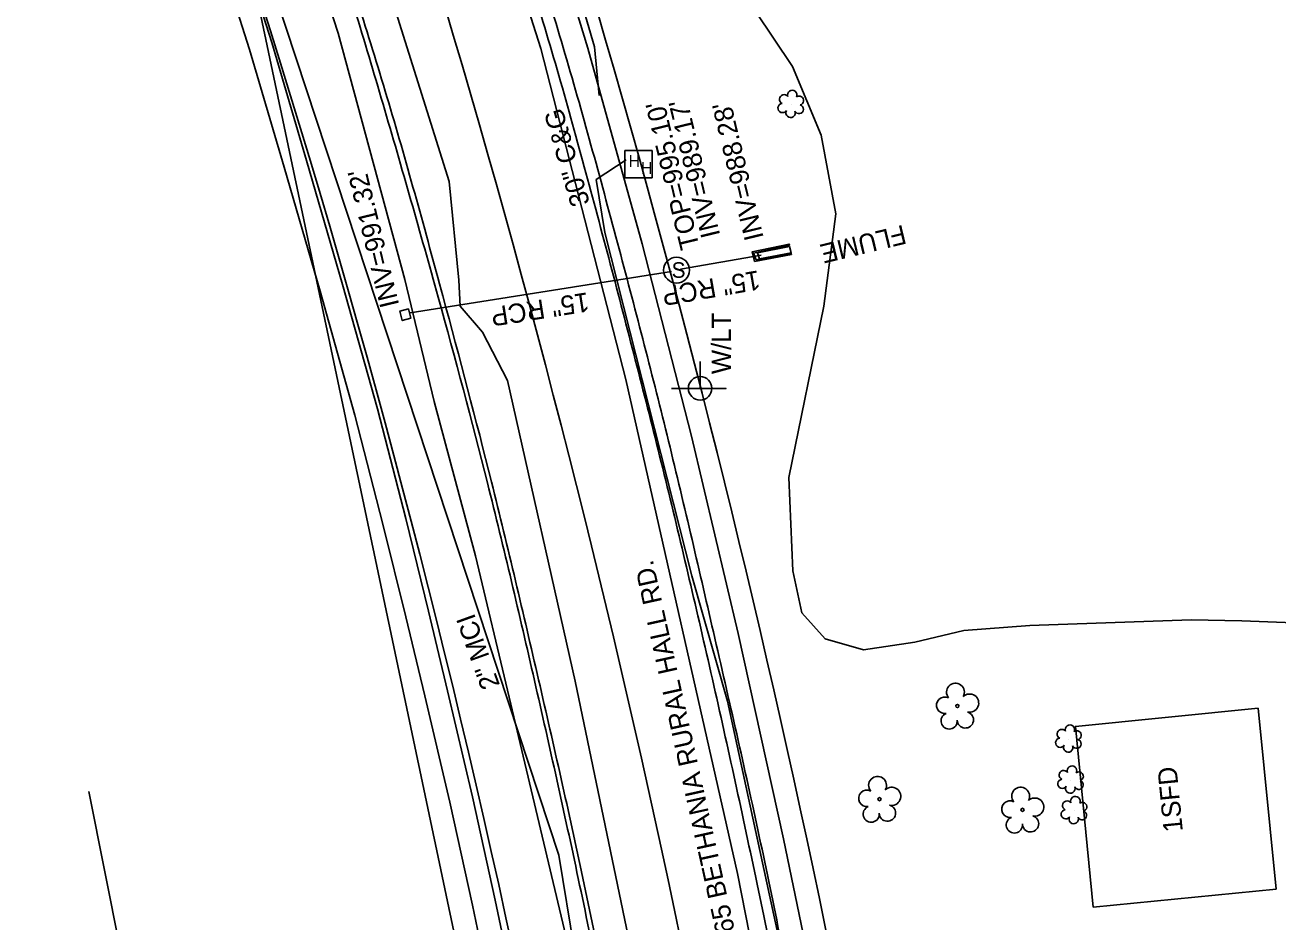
# Model space of a CAD drawing. Extents: x 1614611 to 1617571, y 898867 to 905462.
# Drawn here: x 1616509.7 to 1616770.7, y 902671.5 to 902858.4 of the extents above; entities that cross this region are included whole.
import ezdxf

# ---------------------------------------------------------------- set-up
doc = ezdxf.new("R2010")
doc.units = 0
for name, color, linetype in [('Exist Boundary Watershed Impervious C 09', 7, 'Continuous'), ('Exist Boundary Watershed Residential C 05', 7, 'Continuous'), ('Exist Building', 7, 'Continuous'), ('Exist Building Text', 7, 'Continuous'), ('Exist Roads Curbs Text', 7, 'Continuous'), ('Exist Roads EOP Text', 7, 'Continuous'), ('Exist Structure Minor Head and End Wall Text', 7, 'Continuous'), ('Exist Structure Minor Pipes RCP 15 Inch Invert', 7, 'Continuous'), ('Exist Structure Minor Storm Sewer Manhole Top Elevation', 7, 'Continuous'), ('Exist Utilities Gas UG Line SUE LOS B', 7, 'Continuous'), ('Exist Utilities Power Joint Use Telephone CELL', 7, 'Continuous'), ('Exist Utilities Power Joint Use Telephone Text', 7, 'Continuous'), ('Exist Utilities Telephone Hand Hole CELL', 7, 'Continuous'), ('Exist Utilities Telephone UG Cable SUE LOS B', 7, 'Continuous'), ('Exist Utilities Telephone UG FO SUE LOS B', 7, 'Continuous'), ('Exist Utilities Telephone UG FO SUE LOS C', 7, 'Continuous'), ('Exist Utilities Telephone UG FO SUE LOS C Text', 7, 'Continuous'), ('Exist Utilities Water UG Line SUE LOS B', 7, 'Continuous'), ('Exist Vegetation Shrub CELL', 7, 'Continuous'), ('Exist Vegetation Tree CELL', 7, 'Continuous'), ('Exist Vegetation Woods Line', 7, 'Continuous'), ('Prop Drainage Structure Pipe RCP 15in Class IV', 7, 'Continuous'), ('Prop Drainage Structure Pipe RCP 24in Class IV', 7, 'Continuous'), ('Prop Earthen Structure Head Ditch Label', 7, 'Continuous'), ('Prop Erosion Embankment Toe Protection CELL', 7, 'Continuous'), ('Prop Erosion Embankment Toe Protection with Rip Rap 2 Detail CELL', 7, 'Continuous'), ('Prop Plan Preparation Table Ditch Data CELL', 7, 'Continuous'), ('Raster_Level_2', 7, 'Continuous'), ('Scratch_Level_1', 7, 'Continuous'), ('Scratch_Level_9', 7, 'Continuous')]:
    doc.layers.add(name, color=color, linetype=linetype)

# ---------------------------------------------------------------- blocks, each defined once
blk = doc.blocks.new('EXIST STRUCTURE MINOR STORM SEWER MANHOLE')
at = {"layer": 'Prop Drainage Structure Pipe RCP 15in Class IV'}
blk.add_circle((0, 0), 0.0539, dxfattribs=at)
blk.add_text('S', height=0.065, dxfattribs=at).set_placement((-0.0206, -0.032))

msp = doc.modelspace()

# ---------------------------------------------------------------- linework, layer by layer
at = {"layer": 'Exist Boundary Watershed Impervious C 09'}
msp.add_spline([(1616665.13, 902435.43), (1616660.48, 902479.08), (1616654.89, 902521.26), (1616648.51, 902561.33), (1616641.12, 902603.28), (1616634.46, 902638.28), (1616625.9, 902680.69), (1616616.67, 902721.99), (1616606.86, 902763.22), (1616596.71, 902801.99), (1616585.45, 902842.18), (1616573.19, 902881.5), (1616565.19, 902906.61), (1616557.25, 902931.31), (1616544.89, 902968.22), (1616530.94, 903009.35), (1616518.06, 903047.65)], degree=3, dxfattribs=at)
at = {"layer": 'Exist Boundary Watershed Residential C 05'}
msp.add_spline([(1616609.89, 902892.41), (1616622.17, 902852.43), (1616633.45, 902811.75), (1616643.74, 902771.73), (1616653.39, 902730.67), (1616662.94, 902688.03), (1616671.61, 902645.14)], degree=3, dxfattribs=at)
at = {"layer": 'Exist Building'}
msp.add_lwpolyline([(1616766.61, 902716.05), (1616770.33, 902678.38), (1616732.23, 902674.63), (1616728.52, 902712.29)], close=True, dxfattribs=at)
at = {"layer": 'Exist Utilities Gas UG Line SUE LOS B'}
msp.add_lwpolyline([(1616661.01, 902037.25), (1616663.33, 902064.4), (1616667.18, 902120.35), (1616669.8, 902175.63), (1616670.18, 902203.89), (1616670, 902252.83), (1616667.06, 902308.42), (1616666.18, 902342.89), (1616662.96, 902384.82), (1616659.36, 902418.53), (1616657.17, 902446.04), (1616652.37, 902490.94), (1616648.49, 902520.82), (1616640.31, 902575.63), (1616630.24, 902629.08), (1616624.64, 902659), (1616610.54, 902718.34), (1616603.5, 902747.83), (1616594.95, 902779.96), (1616588.83, 902805.4), (1616574.94, 902856.71), (1616560.06, 902902.39)], dxfattribs=at)
at = {"layer": 'Exist Utilities Power Joint Use Telephone CELL'}
msp.add_line((1616650.33, 902782.7), (1616650.33, 902782.7), dxfattribs=at)
msp.add_lwpolyline([(1616644.39, 902782.7), (1616655.73, 902782.66), (1616650.33, 902782.68), (1616650.33, 902788.32)], dxfattribs=at)
msp.add_circle((1616650.33, 902782.71), 2.45, dxfattribs=at)
at = {"layer": 'Exist Utilities Telephone Hand Hole CELL'}
for p, q in [((1616634.63, 902832.28), (1616634.63, 902826.55)), ((1616640.36, 902832.28), (1616634.63, 902832.28)), ((1616640.36, 902826.55), (1616640.36, 902832.28)), ((1616637.49, 902829.41), (1616637.49, 902829.41)), ((1616634.63, 902826.55), (1616640.36, 902826.55))]:
    msp.add_line(p, q, dxfattribs=at)
at = {"layer": 'Exist Utilities Telephone UG Cable SUE LOS B'}
msp.add_lwpolyline([(1616653.58, 902416.71), (1616663.67, 902417.14), (1616669.74, 902418.75), (1616672.64, 902421.54), (1616661.03, 902530.35), (1616645.59, 902619.16), (1616624.26, 902721.72), (1616610.21, 902784.31), (1616604.98, 902794.39), (1616600.3, 902799.85), (1616600.03, 902805.22), (1616598.01, 902825.81), (1616571.3, 902910.94), (1616549.08, 902977.64), (1616515.65, 903076.73), (1616483.43, 903168.54), (1616464.03, 903218.81), (1616463.64, 903219.2), (1616462.93, 903219.33), (1616457.94, 903217.72), (1616449, 903216.46)], dxfattribs=at)
at = {"layer": 'Exist Utilities Telephone UG FO SUE LOS B'}
for points in [[(1616629.3, 902843.73), (1616628.3, 902853.82), (1616611.3, 902911.93)], [(1616708.77, 902097.06), (1616709.58, 902140.25), (1616710.58, 902218.49), (1616710.01, 902283.99), (1616708.01, 902353.12), (1616701.91, 902435.97), (1616696.63, 902483.57), (1616691.69, 902526.33), (1616686.21, 902567.93), (1616679.63, 902610.92), (1616669.49, 902655.34), (1616656.06, 902717.52), (1616648.63, 902743.65), (1616630.5, 902815.16), (1616628.69, 902826.2), (1616634.94, 902830.28)]]:
    msp.add_lwpolyline(points, dxfattribs=at)
at = {"layer": 'Exist Utilities Telephone UG FO SUE LOS C'}
for p, q in [((1616620.89, 902685.44), (1616551.38, 902896.35)), ((1616538.68, 902619.72), (1616523, 902698.69)), ((1616651.55, 902501.26), (1616620.89, 902685.44))]:
    msp.add_line(p, q, dxfattribs=at)
at = {"layer": 'Exist Utilities Water UG Line SUE LOS B'}
msp.add_lwpolyline([(1616682.85, 901889.35), (1616688.26, 901932.45), (1616696.61, 902016.19), (1616699.26, 902055.42), (1616702.78, 902110.39), (1616705.34, 902181.72), (1616707.31, 902255.35), (1616706.62, 902316.75), (1616703.14, 902377.45), (1616699.12, 902434.84), (1616686.86, 902524.85), (1616669.78, 902622.34), (1616658.13, 902681.62), (1616634.87, 902784.56), (1616617.17, 902853.52), (1616602.15, 902900.61), (1616584.28, 902954.24), (1616571.86, 902993.81)], dxfattribs=at)
at = {"layer": 'Exist Vegetation Shrub CELL'}
for p, q in [((1616669.29, 902841.79), (1616669.29, 902841.79)), ((1616727.14, 902709.57), (1616727.14, 902709.57)), ((1616727.58, 902701.01), (1616727.58, 902701.01)), ((1616728.29, 902694.66), (1616728.29, 902694.66))]:
    msp.add_line(p, q, dxfattribs=at)
for centre, radius, start, end in [((1616667.81, 902842.92), 0.968, 35.8908, 245.4216), ((1616669.52, 902843.83), 0.99, 334.8391, 200.4717), ((1616670.96, 902842.66), 0.929, 284.4567, 126.0861), ((1616667.49, 902841.09), 0.955, 95.1099, 327.9534), ((1616669.16, 902840.11), 0.984, 151.2797, 21.387), ((1616670.92, 902840.86), 0.937, 204.9913, 73.4601), ((1616727.37, 902711.61), 0.99, 334.8391, 200.4717), ((1616725.34, 902708.87), 0.955, 95.1099, 327.9534), ((1616725.66, 902710.7), 0.968, 35.8908, 245.4216), ((1616728.82, 902710.44), 0.929, 284.4567, 126.0861), ((1616727.01, 902707.89), 0.984, 151.2797, 21.387), ((1616728.78, 902708.64), 0.937, 204.9913, 73.4601), ((1616726.1, 902702.14), 0.968, 35.8908, 245.4216), ((1616727.81, 902703.05), 0.99, 334.8391, 200.4717), ((1616729.25, 902701.88), 0.929, 284.4567, 126.0861), ((1616725.78, 902700.31), 0.955, 95.1099, 327.9534), ((1616727.45, 902699.33), 0.984, 151.2797, 21.387), ((1616729.22, 902700.08), 0.937, 204.9913, 73.4601), ((1616726.8, 902695.79), 0.968, 35.8908, 245.4216), ((1616728.51, 902696.7), 0.99, 334.8391, 200.4717), ((1616726.49, 902693.96), 0.955, 95.1099, 327.9534), ((1616729.92, 902693.73), 0.937, 204.9913, 73.4601), ((1616729.96, 902695.53), 0.929, 284.4567, 126.0861), ((1616728.16, 902692.98), 0.984, 151.2797, 21.387)]:
    msp.add_arc(centre, radius, start, end, dxfattribs=at)
at = {"layer": 'Exist Vegetation Tree CELL'}
for p, q in [((1616703.92, 902716.54), (1616703.92, 902716.54)), ((1616687.69, 902697.12), (1616687.69, 902697.12)), ((1616717.49, 902694.89), (1616717.49, 902694.89))]:
    msp.add_line(p, q, dxfattribs=at)
for centre in [(1616703.92, 902716.54), (1616687.69, 902697.12), (1616717.49, 902694.89)]:
    msp.add_circle(centre, 0.326, dxfattribs=at)
for centre, radius, start, end in [((1616703.53, 902719.41), 1.86, 330.1651, 219.7134), ((1616701.31, 902716.69), 1.73, 62.6636, 279.3457), ((1616706.47, 902717.13), 1.9, 257.1011, 134.1999), ((1616705.59, 902713.64), 1.7, 181.2822, 74.56), ((1616702.21, 902713.42), 1.69, 111.5671, 6.231), ((1616687.3, 902700), 1.86, 330.1651, 219.7134), ((1616690.23, 902697.71), 1.9, 257.1011, 134.1999), ((1616717.11, 902697.76), 1.86, 330.1651, 219.7134), ((1616685.08, 902697.28), 1.73, 62.6636, 279.3457), ((1616714.89, 902695.04), 1.73, 62.6636, 279.3457), ((1616720.04, 902695.47), 1.9, 257.1011, 134.1999), ((1616685.98, 902694), 1.69, 111.5671, 6.231), ((1616689.36, 902694.22), 1.7, 181.2822, 74.56), ((1616715.79, 902691.76), 1.69, 111.5671, 6.231), ((1616719.17, 902691.99), 1.7, 181.2822, 74.56)]:
    msp.add_arc(centre, radius, start, end, dxfattribs=at)
at = {"layer": 'Exist Vegetation Woods Line'}
for points in [[(1616668.84, 902764.14), (1616676.13, 902799.8), (1616678.62, 902819.06), (1616675.55, 902835.43), (1616669.55, 902849.77), (1616650.05, 902878.92), (1616647.54, 902886.56), (1616646.67, 902894.57), (1616648.67, 902902.57), (1616653.53, 902907.32), (1616659.81, 902910.93), (1616671.71, 902909.53), (1616681.45, 902908.58), (1616696.21, 902909.36), (1616708.59, 902912.5), (1616716.51, 902914.22), (1616725.21, 902914.81), (1616737.14, 902914.37), (1616745.55, 902915.12), (1616761.84, 902918.71), (1616771.16, 902920.71), (1616780.96, 902922.08), (1616785.68, 902921.01), (1616787.32, 902918.96)], [(1616774.05, 902733.84), (1616763.17, 902734.3), (1616752.61, 902734.48), (1616719.04, 902733.33), (1616705.29, 902732.25), (1616695.04, 902729.84), (1616684.36, 902728.2), (1616676.4, 902730.52), (1616671.49, 902735.94), (1616669.67, 902744.68), (1616668.84, 902764.14)]]:
    msp.add_lwpolyline(points, dxfattribs=at)
at = {"layer": 'Prop Drainage Structure Pipe RCP 24in Class IV'}
msp.add_lwpolyline([(1616669.36, 902810.59), (1616661.68, 902809.13), (1616661.19, 902811.17), (1616668.87, 902812.75), (1616668.95, 902812.54), (1616661.48, 902810.88), (1616662, 902809.48), (1616669.32, 902810.85), (1616669.36, 902810.59)], dxfattribs=at)
at = {"layer": 'Prop Earthen Structure Head Ditch Label'}
msp.add_line((1616010.65, 905462.23), (1616993.32, 900797.76), dxfattribs=at)
for centre, radius, start, end in [((1614325.74, 902186.35), 2400, 9.05, 18.76383), ((1614538.44, 902221.24), 2120, 353.93806, 18.41557)]:
    msp.add_arc(centre, radius, start, end, dxfattribs=at)
at = {"layer": 'Prop Erosion Embankment Toe Protection CELL'}
msp.add_lwpolyline([(1616590.07, 902797.3), (1616588.28, 902796.82), (1616587.76, 902798.76), (1616589.55, 902799.24)], close=True, dxfattribs=at)
at = {"layer": 'Prop Plan Preparation Table Ditch Data CELL'}
for p, q in [((1616663.03, 902810.45), (1616646.24, 902807.53)), ((1616644.38, 902807.05), (1616589.89, 902798.47))]:
    msp.add_line(p, q, dxfattribs=at)
at = {"layer": 'Raster_Level_2'}
msp.add_arc((1614346.11, 902189.59), 2349.37, 9.05, 19.17682, dxfattribs=at)
at = {"layer": 'Scratch_Level_1'}
for points in [[(1616614.65, 902893.86), (1616626.96, 902853.56), (1616638.24, 902812.83), (1616648.55, 902772.75), (1616658.26, 902731.61), (1616667.73, 902688.88), (1616676.31, 902647.23)], [(1616588.99, 902755.56), (1616583.12, 902778.42), (1616575.83, 902804.32), (1616568.31, 902830.2), (1616561.1, 902854.77), (1616553.97, 902877.13), (1616549.79, 902889.69), (1616545.16, 902888.13)], [(1616584.24, 902754.42), (1616578.41, 902777.13), (1616571.14, 902802.96), (1616563.63, 902828.8), (1616556.43, 902853.31), (1616549.33, 902875.6), (1616545.16, 902888.13)], [(1616669.29, 902810.95), (1616662.67, 902809.69), (1616662.27, 902810.92), (1616668.94, 902812.24), (1616669.29, 902810.95)], [(1616635.2, 902482.65), (1616632, 902508.68), (1616628.75, 902531.69), (1616625.18, 902554.85), (1616621.17, 902580.26), (1616616.86, 902604.66), (1616612.24, 902629.12), (1616608.13, 902650.05), (1616602.88, 902675.06), (1616598.15, 902696.53), (1616592.96, 902718.62), (1616589.01, 902735.14), (1616584.24, 902754.42)], [(1616640.05, 902483.2), (1616636.84, 902509.29), (1616633.58, 902532.38), (1616630.01, 902555.58), (1616625.98, 902581.04), (1616621.66, 902605.52), (1616617.03, 902630.01), (1616612.92, 902650.99), (1616607.66, 902676.06), (1616602.92, 902697.58), (1616597.72, 902719.72), (1616593.76, 902736.26), (1616588.99, 902755.56)]]:
    msp.add_lwpolyline(points, dxfattribs=at)
at = {"layer": 'Scratch_Level_9'}
for points in [[(1616664.02, 902435.24), (1616659.23, 902479.02), (1616653.86, 902521.19), (1616647.48, 902561.19), (1616640.05, 902603.13), (1616633.52, 902638.17), (1616624.95, 902680.56), (1616615.82, 902721.84), (1616606.01, 902763.05), (1616595.75, 902801.7), (1616584.26, 902841.93), (1616572.3, 902881.24), (1616564.26, 902906.37), (1616556.43, 902931.12), (1616543.99, 902967.9), (1616530.08, 903008.97), (1616517.05, 903047.39)], [(1616607.54, 902891.47), (1616619.8, 902851.65), (1616630.95, 902811.11), (1616641.26, 902771.18), (1616651.06, 902730.14), (1616660.51, 902687.43), (1616669.23, 902644.79), (1616673.27, 902623.83), (1616676.02, 902609.12), (1616683.43, 902567.11), (1616690.02, 902525.73), (1616695.57, 902482.82), (1616700.47, 902437.88)]]:
    msp.add_spline(points, degree=3, dxfattribs=at)

# ---------------------------------------------------------------- block references
at = {"layer": 'Prop Drainage Structure Pipe RCP 15in Class IV', "xscale": 50, "yscale": 50}
msp.add_blockref('EXIST STRUCTURE MINOR STORM SEWER MANHOLE', (1616645.42, 902807.33), dxfattribs=at)

# ---------------------------------------------------------------- texts
at = {"layer": 'Exist Building Text'}
msp.add_text('1SFD', height=4, rotation=95.6348, dxfattribs=at).set_placement((1616750.91, 902690.46))
at = {"layer": 'Exist Roads Curbs Text'}
msp.add_text('30" C&G', height=4, rotation=106.186, dxfattribs=at).set_placement((1616627.39, 902821.27))
at = {"layer": 'Exist Roads EOP Text'}
msp.add_text('NC 65 BETHANIA RURAL HALL RD.', height=4, rotation=102.4863, dxfattribs=at).set_placement((1616659.6, 902660.68))
at = {"layer": 'Exist Structure Minor Head and End Wall Text'}
msp.add_text('FLUME', height=4, rotation=193.5685, dxfattribs=at).set_placement((1616692.66, 902816.82))
at = {"layer": 'Exist Structure Minor Pipes RCP 15 Inch Invert'}
for s, p in [("INV=989.17'", (1616654.54, 902814.6)), ("INV=988.28'", (1616663.6, 902814.07)), ("INV=991.32'", (1616587.66, 902800.08))]:
    msp.add_text(s, height=4, rotation=103.6417, dxfattribs=at).set_placement(p)
at = {"layer": 'Exist Structure Minor Storm Sewer Manhole Top Elevation'}
msp.add_text("TOP=995.10'", height=4, rotation=103.6417, dxfattribs=at).set_placement((1616650.22, 902812.18))
at = {"layer": 'Exist Utilities Power Joint Use Telephone Text'}
msp.add_text('W/LT', height=4, rotation=90, dxfattribs=at).set_placement((1616656.75, 902785.67))
at = {"layer": 'Exist Utilities Telephone Hand Hole CELL'}
for p in [(1616635.41, 902828.82), (1616637.98, 902827.36)]:
    msp.add_text('H', height=2.5, dxfattribs=at).set_placement(p)
at = {"layer": 'Exist Utilities Telephone UG FO SUE LOS C Text'}
msp.add_text('2" MCI', height=4, rotation=109.8827, dxfattribs=at).set_placement((1616608.66, 902720.87))
at = {"layer": 'Prop Erosion Embankment Toe Protection with Rip Rap 2 Detail CELL'}
for rotation, p in [(189.8657, (1616662.45, 902807.31)), (188.9503, (1616626.86, 902802.73))]:
    msp.add_text('15" RCP', height=4, rotation=rotation, dxfattribs=at).set_placement(p)

doc.saveas('drawing.dxf')
